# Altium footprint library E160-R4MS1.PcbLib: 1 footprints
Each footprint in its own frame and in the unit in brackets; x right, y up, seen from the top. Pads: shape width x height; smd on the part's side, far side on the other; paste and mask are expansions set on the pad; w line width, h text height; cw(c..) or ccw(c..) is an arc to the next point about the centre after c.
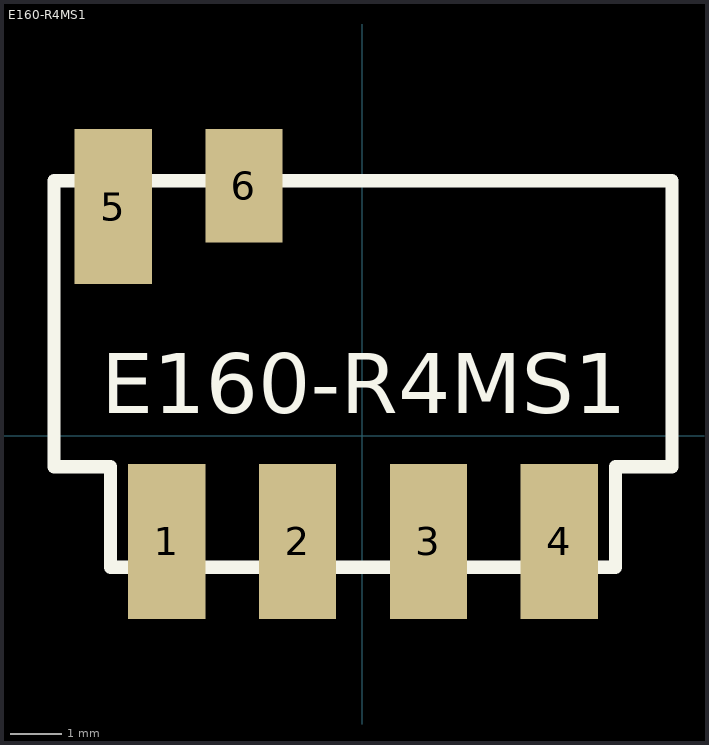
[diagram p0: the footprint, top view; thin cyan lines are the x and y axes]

## E160-R4MS1 [mm]
pads (6):
  rect 1.5x3 smd mask+0: 1(-3.798,-2.053) 2(-1.258,-2.053) 3(1.282,-2.053) 4(3.822,-2.053) 5(-4.838,4.447)
  rect 1.5x2.2 smd mask+0: 6(-2.298,4.847)
Top Overlay:
  lines w0.254: -5.988,-0.603 -4.888,-0.603 -4.888,-2.553 4.912,-2.553 4.912,-0.603 6.012,-0.603 6.012,4.947 -5.988,4.947 -5.988,-0.603
  text "E160-R4MS1" at -5.064,0.049 h2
